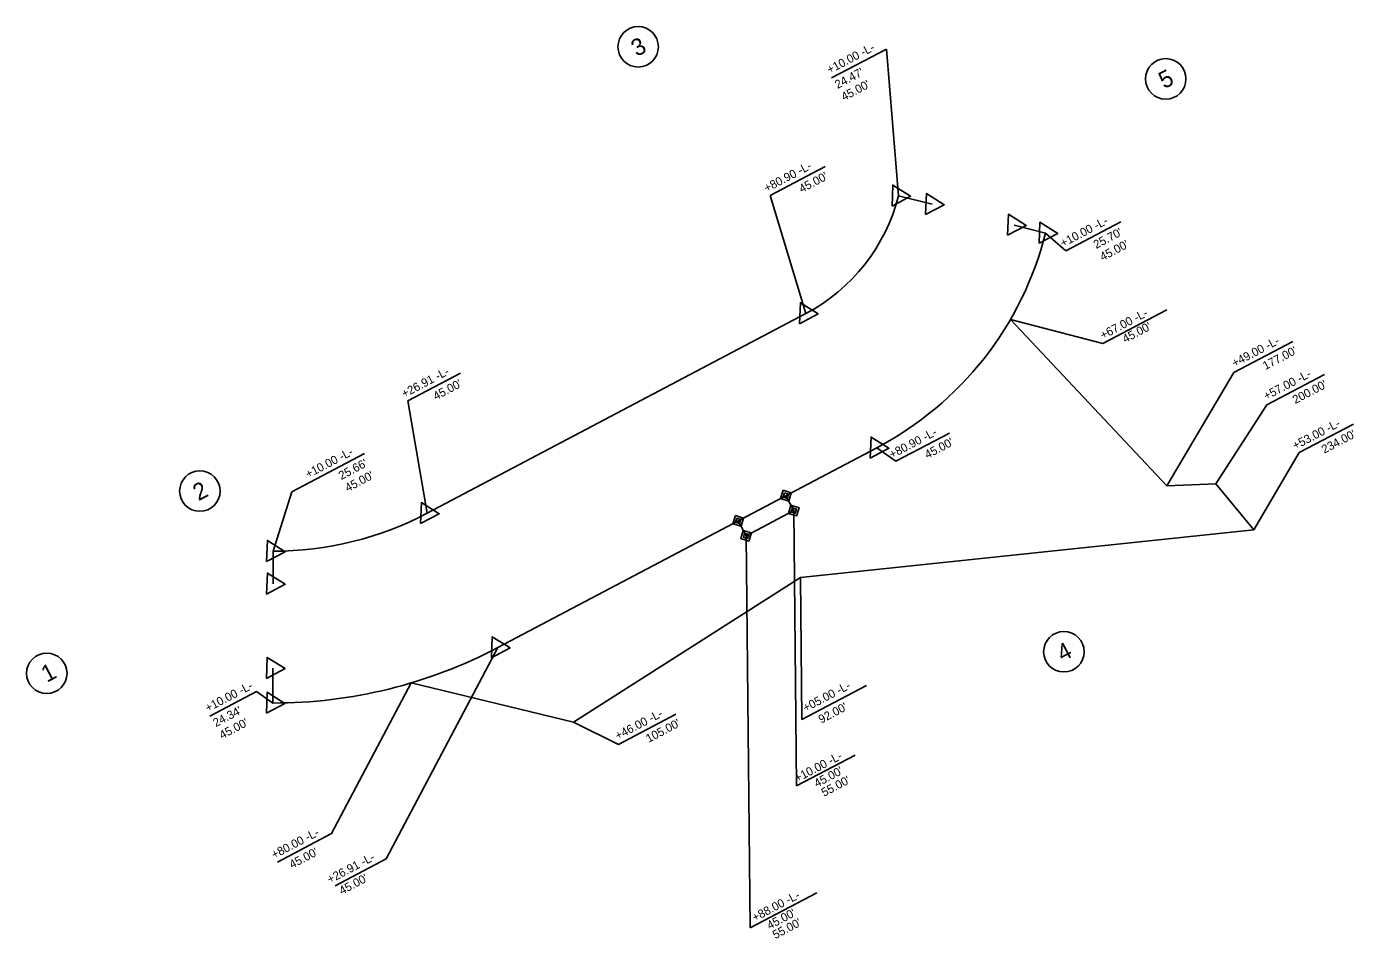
# Model space of a CAD drawing. Extents: x 1381317 to 1382104, y 595264 to 595804.
import ezdxf

# ---------------------------------------------------------------- set-up
doc = ezdxf.new("R2010")
doc.units = 0
for name, color, linetype in [('Prop Easement Permanent Drainage', 7, 'Continuous'), ('Prop Easement Permanent Drainage Station Offsets', 7, 'Continuous'), ('Prop Easement Temporary Utility', 7, 'Continuous'), ('Prop Easement Temporary Utility Station Offsets', 7, 'Continuous'), ('Prop Parcel Number CELL', 7, 'Continuous'), ('Prop Parcel Number Text', 7, 'Continuous'), ('Prop ROW Marker CELL', 7, 'Continuous'), ('Prop ROW Permanent Easement CELL', 7, 'Continuous'), ('Prop ROW RW Lines', 7, 'Continuous'), ('Prop ROW Station Offsets', 7, 'Continuous')]:
    doc.layers.add(name, color=color, linetype=linetype)

msp = doc.modelspace()

# ---------------------------------------------------------------- linework, layer by layer
at = {"layer": 'Prop Easement Permanent Drainage'}
for p, q in [((1381772.06, 595517.23), (1381767.39, 595526.07)), ((1381743.75, 595502.31), (1381772.06, 595517.23)), ((1381739.09, 595511.15), (1381743.75, 595502.31))]:
    msp.add_line(p, q, dxfattribs=at)
at = {"layer": 'Prop Easement Permanent Drainage Station Offsets'}
for p, q in [((1381772.06, 595517.23), (1381773.73, 595353.94)), ((1381743.75, 595502.31), (1381746.13, 595269.8)), ((1381773.73, 595353.94), (1381808.55, 595372.3)), ((1381746.13, 595269.8), (1381785.63, 595290.62))]:
    msp.add_line(p, q, dxfattribs=at)
at = {"layer": 'Prop Easement Temporary Utility'}
for p, q in [((1381900.51, 595630.5), (1381993.28, 595531.93)), ((1381993.28, 595531.93), (1382022.32, 595533.12)), ((1382022.32, 595533.12), (1382044.82, 595505.87)), ((1381776.04, 595477.5), (1382044.82, 595505.87)), ((1381641.46, 595391.85), (1381776.04, 595477.5)), ((1381545.09, 595415.01), (1381641.46, 595391.85))]:
    msp.add_line(p, q, dxfattribs=at)
at = {"layer": 'Prop Easement Temporary Utility Station Offsets'}
for p, q in [((1381955.36, 595616.22), (1381993.37, 595636.25)), ((1381900.51, 595630.5), (1381955.36, 595616.22)), ((1382032.94, 595599), (1382067.92, 595617.44)), ((1381993.28, 595531.93), (1382032.94, 595599)), ((1382052.61, 595579.93), (1382086.7, 595597.91)), ((1382022.32, 595533.12), (1382052.61, 595579.93)), ((1382071.85, 595551.58), (1382103.91, 595568.48)), ((1382044.82, 595505.87), (1382071.85, 595551.58)), ((1381776.04, 595477.5), (1381776.91, 595393.31)), ((1381545.09, 595415.01), (1381497.9, 595325.68)), ((1381776.91, 595393.31), (1381815.08, 595413.43)), ((1381641.46, 595391.85), (1381668.08, 595378.49)), ((1381668.08, 595378.49), (1381702.16, 595396.46)), ((1381497.9, 595325.68), (1381465.79, 595308.75))]:
    msp.add_line(p, q, dxfattribs=at)
at = {"layer": 'Prop Parcel Number CELL'}
for p, q in [((1381679.77, 595792.2), (1381679.77, 595792.2)), ((1381992.61, 595773.17), (1381992.61, 595773.17)), ((1381419.84, 595528.79), (1381419.84, 595528.79)), ((1381932.24, 595433.54), (1381932.24, 595433.54)), ((1381329.05, 595420.73), (1381329.05, 595420.73))]:
    msp.add_line(p, q, dxfattribs=at)
for centre in [(1381679.77, 595792.2), (1381992.61, 595773.17), (1381419.84, 595528.79), (1381932.24, 595433.54), (1381329.05, 595420.73)]:
    msp.add_circle(centre, 12, dxfattribs=at)
at = {"layer": 'Prop ROW Marker CELL'}
for p, q in [((1381834.15, 595703.83), (1381834.15, 595703.83)), ((1381854.05, 595698.8), (1381854.05, 595698.8)), ((1381902.69, 595686.52), (1381902.69, 595686.52)), ((1381921.41, 595681.79), (1381921.41, 595681.79)), ((1381779.29, 595634.09), (1381779.29, 595634.09)), ((1381821.27, 595554.47), (1381821.27, 595554.47)), ((1381554.62, 595515.64), (1381554.62, 595515.64)), ((1381463.29, 595493.14), (1381463.29, 595493.14)), ((1381463.26, 595473.8), (1381463.26, 595473.8)), ((1381596.59, 595436.03), (1381596.59, 595436.03)), ((1381463.16, 595423.8), (1381463.16, 595423.8)), ((1381463.12, 595403.14), (1381463.12, 595403.14))]:
    msp.add_line(p, q, dxfattribs=at)
for points in [[(1381830.3, 595697.73), (1381830.79, 595710.2), (1381841.35, 595703.56)], [(1381850.2, 595692.7), (1381850.69, 595705.17), (1381861.25, 595698.53)], [(1381898.84, 595680.42), (1381899.33, 595692.89), (1381909.9, 595686.25)], [(1381917.56, 595675.69), (1381918.05, 595688.16), (1381928.61, 595681.52)], [(1381775.44, 595627.99), (1381775.94, 595640.46), (1381786.5, 595633.82)], [(1381817.42, 595548.38), (1381817.91, 595560.84), (1381828.47, 595554.21)], [(1381550.77, 595509.54), (1381551.26, 595522.01), (1381561.82, 595515.37)], [(1381459.44, 595487.04), (1381459.94, 595499.51), (1381470.5, 595492.87)], [(1381459.41, 595467.7), (1381459.9, 595480.17), (1381470.46, 595473.53)], [(1381592.74, 595429.93), (1381593.23, 595442.4), (1381603.8, 595435.76)], [(1381459.31, 595417.7), (1381459.8, 595430.17), (1381470.37, 595423.53)], [(1381459.27, 595397.04), (1381459.76, 595409.51), (1381470.32, 595402.87)]]:
    msp.add_lwpolyline(points, close=True, dxfattribs=at)
at = {"layer": 'Prop ROW Permanent Easement CELL'}
for p, q in [((1381767.39, 595526.08), (1381767.39, 595526.08)), ((1381772.06, 595517.23), (1381772.06, 595517.23)), ((1381739.09, 595511.15), (1381739.09, 595511.15)), ((1381743.75, 595502.31), (1381743.75, 595502.31))]:
    msp.add_line(p, q, dxfattribs=at)
for points in [[(1381765.72, 595529.26), (1381770.58, 595527.75), (1381769.07, 595522.89), (1381764.21, 595524.4)], [(1381766.56, 595527.67), (1381768.99, 595526.91), (1381768.23, 595524.48), (1381765.8, 595525.23)], [(1381770.38, 595520.41), (1381775.24, 595518.91), (1381773.74, 595514.04), (1381768.87, 595515.55)], [(1381771.22, 595518.82), (1381773.65, 595518.07), (1381772.9, 595515.64), (1381770.47, 595516.39)], [(1381737.41, 595514.34), (1381742.27, 595512.83), (1381740.77, 595507.97), (1381735.9, 595509.47)], [(1381738.25, 595512.74), (1381740.68, 595511.99), (1381739.93, 595509.56), (1381737.5, 595510.31)], [(1381742.07, 595505.49), (1381746.94, 595503.98), (1381745.43, 595499.12), (1381740.57, 595500.63)], [(1381742.91, 595503.9), (1381745.34, 595503.14), (1381744.59, 595500.71), (1381742.16, 595501.47)]]:
    msp.add_lwpolyline(points, close=True, dxfattribs=at)
at = {"layer": 'Prop ROW RW Lines'}
for p, q in [((1381834.15, 595703.83), (1381854.05, 595698.8)), ((1381902.69, 595686.52), (1381921.41, 595681.79)), ((1381554.62, 595515.64), (1381779.29, 595634.09)), ((1381596.59, 595436.03), (1381821.27, 595554.47)), ((1381463.26, 595473.8), (1381463.29, 595493.14)), ((1381463.12, 595403.14), (1381463.16, 595423.8))]:
    msp.add_line(p, q, dxfattribs=at)
for centre, radius, start, end in [((1381728.46, 595730.51), 109, 297.7977, 345.82963), ((1381728.46, 595730.51), 199, 297.7977, 345.82963), ((1381463.68, 595688.14), 195, 269.88725, 297.7977), ((1381463.68, 595688.14), 285, 269.88725, 297.7977)]:
    msp.add_arc(centre, radius, start, end, dxfattribs=at)
at = {"layer": 'Prop ROW Station Offsets'}
for p, q in [((1381826.94, 595790.89), (1381794.5, 595773.79)), ((1381834.15, 595703.83), (1381826.94, 595790.89)), ((1381757.99, 595704.04), (1381790.73, 595721.29)), ((1381779.29, 595634.09), (1381757.99, 595704.04)), ((1381921.41, 595681.79), (1381933.31, 595671.24)), ((1381933.31, 595671.24), (1381965.99, 595688.47)), ((1381543.27, 595582.3), (1381574.31, 595598.66)), ((1381554.62, 595515.64), (1381543.27, 595582.3)), ((1381832.6, 595546.45), (1381864.4, 595563.22)), ((1381474.46, 595528.36), (1381517.46, 595551.03)), ((1381821.27, 595554.47), (1381832.6, 595546.45)), ((1381463.29, 595493.14), (1381474.46, 595528.36)), ((1381596.59, 595436.03), (1381530.38, 595310.69)), ((1381453.42, 595410), (1381425.77, 595395.42)), ((1381463.12, 595403.14), (1381453.42, 595410)), ((1381500.12, 595294.73), (1381530.38, 595310.69))]:
    msp.add_line(p, q, dxfattribs=at)

# ---------------------------------------------------------------- texts
at = {"layer": 'Prop Easement Permanent Drainage Station Offsets'}
for s, p in [('+10.00 -L-', (1381774.16, 595356)), ("45.00'", (1381785.72, 595352.96)), ("55.00'", (1381790.02, 595347.49)), ('+88.00 -L-', (1381748.97, 595273.39)), ("45.00'", (1381757.73, 595268.76)), ("55.00'", (1381761.08, 595263.07))]:
    msp.add_text(s, height=5, rotation=27.7977, dxfattribs=at).set_placement(p)
at = {"layer": 'Prop Easement Temporary Utility Station Offsets'}
for s, p in [('+67.00 -L-', (1381955.4, 595618.57)), ("45.00'", (1381968.59, 595616.47)), ('+49.00 -L-', (1382033.47, 595602.11)), ("177.00'", (1382051.75, 595600.44)), ('+57.00 -L-', (1382052.26, 595582.57)), ("200.00'", (1382069.48, 595580.35)), ('+53.00 -L-', (1382069.47, 595553.15)), ("234.00'", (1382086.68, 595550.92)), ('+05.00 -L-', (1381779.07, 595397.68)), ("92.00'", (1381788.33, 595390.85)), ('+46.00 -L-', (1381667.72, 595381.13)), ("105.00'", (1381685.99, 595379.46)), ('+80.00 -L-', (1381463.92, 595310.59)), ("45.00'", (1381474.5, 595304.86))]:
    msp.add_text(s, height=5, rotation=27.7977, dxfattribs=at).set_placement(p)
at = {"layer": 'Prop Parcel Number Text'}
for s, p in [('3', (1381678.94, 595786.12)), ('5', (1381991.76, 595767.06)), ('2', (1381419.06, 595522.73)), ('4', (1381931.43, 595427.46)), ('1', (1381329.09, 595415.09))]:
    msp.add_text(s, height=10, rotation=27.7977, dxfattribs=at).set_placement(p)
at = {"layer": 'Prop ROW Station Offsets'}
for s, p in [('+10.00 -L-', (1381793.34, 595776.01)), ("24.47'", (1381798, 595767.16)), ("45.00'", (1381801.79, 595759.97)), ('+80.90 -L-', (1381756.03, 595705.83)), ("45.00'", (1381776.75, 595705.45)), ('+10.00 -L-', (1381931.75, 595673.25)), ("25.70'", (1381951.4, 595672.3)), ("45.00'", (1381955.19, 595665.12)), ('+26.91 -L-', (1381541.07, 595583.96)), ("45.00'", (1381559.79, 595582.53)), ('+80.90 -L-', (1381830.28, 595547.92)), ("45.00'", (1381851.32, 595547.84)), ('+10.00 -L-', (1381484.07, 595536.26)), ("25.66'", (1381503.73, 595535.32)), ("45.00'", (1381507.52, 595528.13)), ('+10.00 -L-', (1381424.6, 595397.63)), ("24.34'", (1381429.26, 595388.78)), ("45.00'", (1381433.05, 595381.6)), ('+26.91 -L-', (1381496.95, 595295.96)), ("45.00'", (1381504.02, 595289.32))]:
    msp.add_text(s, height=5, rotation=27.7977, dxfattribs=at).set_placement(p)

doc.saveas('drawing.dxf')
